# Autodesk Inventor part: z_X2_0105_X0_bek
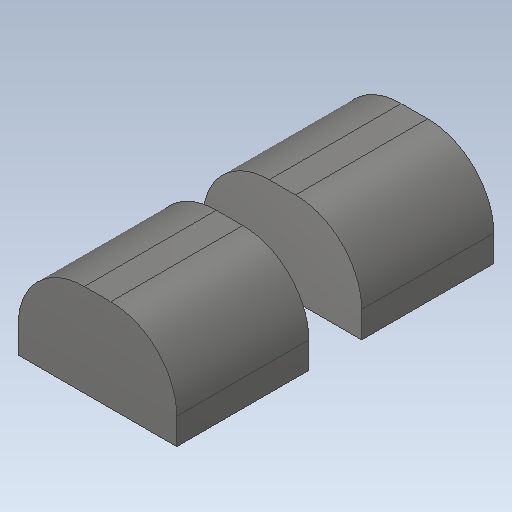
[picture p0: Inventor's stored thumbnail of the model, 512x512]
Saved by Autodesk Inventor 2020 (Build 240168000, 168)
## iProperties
Created: 2015-11
Part Number: z_X2_0105_X0_bek
Material: solidworks materials|Guma|79
Document SubType Name: Modeling
Designer: Tomasz
Density: 1 g/cm^3
Appearance: 76,76,76
Sending System: SolidWorks 2017
Last Author: Tomasz
Last Saved: 2017-11-19
Author: Tomasz
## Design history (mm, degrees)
feature "Imported1"
feature "Imported2"
node "Bryła1"
node "Bryła2"
